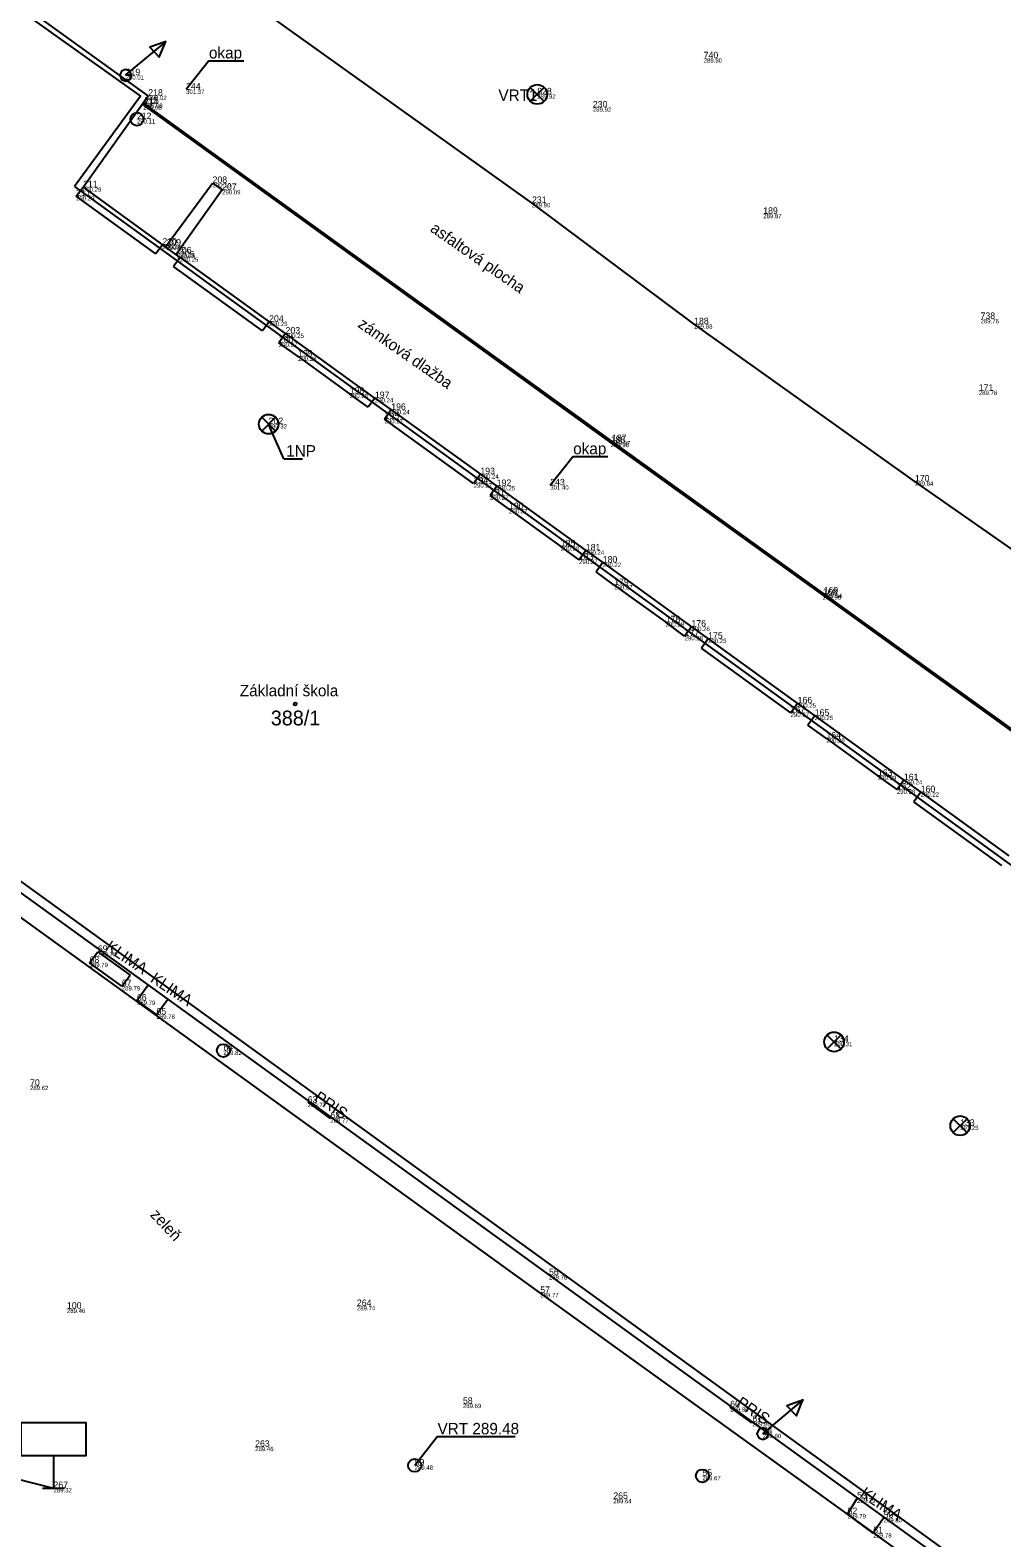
# Model space of a CAD drawing. Extents: x -805057 to -804930, y -994399 to -994240.
# Drawn here: x -805017.71 to -804995.35, y -994342.6 to -994307.89 of the extents above; entities that cross this region are included whole.
import ezdxf

# ---------------------------------------------------------------- set-up
doc = ezdxf.new("R2010")
doc.units = 0
for name, color, linetype in [('bod cislo', 7, 'Continuous'), ('bod pozice', 7, 'Continuous'), ('bod výška', 7, 'Continuous'), ('budova', 7, 'Continuous'), ('kanalizace', 7, 'Continuous'), ('Katastralni mapa', 7, 'Continuous'), ('klima', 7, 'Continuous'), ('komunikace', 7, 'Continuous'), ('označník', 7, 'Continuous'), ('podlaha', 7, 'Continuous'), ('popis', 7, 'Continuous'), ('PRIS', 7, 'Continuous'), ('svod', 7, 'Continuous'), ('vrt', 7, 'Continuous'), ('zemnění', 7, 'Continuous')]:
    doc.layers.add(name, color=color, linetype=linetype)

msp = doc.modelspace()

# ---------------------------------------------------------------- linework, layer by layer
at = {"layer": 'bod pozice'}
for p, q in [((-805002.21, -994308.54), (-805002.21, -994308.54)), ((-805015.51, -994308.93), (-805015.51, -994308.93)), ((-805014.989, -994309.4), (-805014.989, -994309.4)), ((-805014.989, -994309.4), (-805014.989, -994309.4)), ((-805014.12, -994309.26), (-805014.12, -994309.26)), ((-805006.04, -994309.37), (-805006.04, -994309.37)), ((-805015.1, -994309.62), (-805015.1, -994309.62)), ((-805015.08, -994309.58), (-805015.08, -994309.58)), ((-805004.76, -994309.67), (-805004.76, -994309.67)), ((-805015.25, -994309.94), (-805015.25, -994309.94)), ((-805013.51, -994311.41), (-805013.51, -994311.41)), ((-805016.649, -994311.71), (-805016.649, -994311.71)), ((-805016.49, -994311.509), (-805016.49, -994311.509)), ((-805013.29, -994311.57), (-805013.29, -994311.57)), ((-805006.16, -994311.87), (-805006.16, -994311.87)), ((-805000.84, -994312.12), (-805000.84, -994312.12)), ((-805014.663, -994312.829), (-805014.663, -994312.829)), ((-805014.57, -994312.85), (-805014.57, -994312.85)), ((-805014.33, -994313.03), (-805014.33, -994313.03)), ((-805014.259, -994313.121), (-805014.259, -994313.121)), ((-805012.209, -994314.602), (-805012.209, -994314.602)), ((-804995.84, -994314.54), (-804995.84, -994314.54)), ((-805011.831, -994314.875), (-805011.831, -994314.875)), ((-805002.43, -994314.66), (-805002.43, -994314.66)), ((-805011.983, -994315.085), (-805011.983, -994315.085)), ((-805011.541, -994315.405), (-805011.541, -994315.405)), ((-805010.356, -994316.262), (-805010.356, -994316.262)), ((-804995.88, -994316.19), (-804995.88, -994316.19)), ((-805009.775, -994316.361), (-805009.775, -994316.361)), ((-805009.399, -994316.632), (-805009.399, -994316.632)), ((-805012.22, -994316.96), (-805012.22, -994316.96)), ((-805009.552, -994316.844), (-805009.552, -994316.844)), ((-805004.35, -994317.39), (-805004.35, -994317.39)), ((-805004.32, -994317.35), (-805004.32, -994317.35)), ((-805007.503, -994318.325), (-805007.503, -994318.325)), ((-805007.349, -994318.113), (-805007.349, -994318.113)), ((-805006.972, -994318.385), (-805006.972, -994318.385)), ((-805005.74, -994318.37), (-805005.74, -994318.37)), ((-804997.35, -994318.28), (-804997.35, -994318.28)), ((-805007.125, -994318.597), (-805007.125, -994318.597)), ((-805006.688, -994318.915), (-805006.688, -994318.915)), ((-805005.499, -994319.775), (-805005.499, -994319.775)), ((-805005.077, -994320.08), (-805005.077, -994320.08)), ((-805004.922, -994319.867), (-805004.922, -994319.867)), ((-805004.533, -994320.148), (-805004.533, -994320.148)), ((-805004.269, -994320.666), (-805004.269, -994320.666)), ((-804999.45, -994320.86), (-804999.45, -994320.86)), ((-804999.47, -994320.9), (-804999.47, -994320.9)), ((-805003.085, -994321.522), (-805003.085, -994321.522)), ((-805002.648, -994321.838), (-805002.648, -994321.838)), ((-805002.492, -994321.622), (-805002.492, -994321.622)), ((-805002.108, -994321.9), (-805002.108, -994321.9)), ((-805000.21, -994323.601), (-805000.21, -994323.601)), ((-805000.049, -994323.387), (-805000.049, -994323.387)), ((-804999.655, -994323.672), (-804999.655, -994323.672)), ((-804999.387, -994324.195), (-804999.387, -994324.195)), ((-804998.201, -994325.054), (-804998.201, -994325.054)), ((-804997.764, -994325.371), (-804997.764, -994325.371)), ((-804997.604, -994325.154), (-804997.604, -994325.154)), ((-804997.217, -994325.433), (-804997.217, -994325.433)), ((-805016.15, -994329.11), (-805016.15, -994329.11)), ((-805016.34, -994329.36), (-805016.34, -994329.36)), ((-805015.598, -994329.896), (-805015.598, -994329.896)), ((-805015.25, -994330.23), (-805015.25, -994330.23)), ((-805014.8, -994330.55), (-805014.8, -994330.55)), ((-804999.21, -994331.18), (-804999.21, -994331.18)), ((-805013.26, -994331.38), (-805013.26, -994331.38)), ((-805011.32, -994332.58), (-805011.32, -994332.58)), ((-805010.8, -994332.94), (-805010.8, -994332.94)), ((-804996.31, -994333.11), (-804996.31, -994333.11)), ((-805005.77, -994336.55), (-805005.77, -994336.55)), ((-805005.97, -994336.96), (-805005.97, -994336.96)), ((-805016.86, -994337.32), (-805016.86, -994337.32)), ((-805010.19, -994337.26), (-805010.19, -994337.26)), ((-805007.75, -994339.51), (-805007.75, -994339.51)), ((-805001.6, -994339.59), (-805001.6, -994339.59)), ((-805001.09, -994339.93), (-805001.09, -994339.93)), ((-805000.85, -994340.2), (-805000.85, -994340.2)), ((-805012.53, -994340.5), (-805012.53, -994340.5)), ((-805008.86, -994340.93), (-805008.86, -994340.93)), ((-805002.24, -994341.17), (-805002.24, -994341.17)), ((-805017.17, -994341.45), (-805017.17, -994341.45)), ((-805004.29, -994341.7), (-805004.29, -994341.7)), ((-804998.68, -994341.69), (-804998.68, -994341.69)), ((-804998.9, -994342.05), (-804998.9, -994342.05)), ((-804998.07, -994342.14), (-804998.07, -994342.14)), ((-804998.31, -994342.49), (-804998.31, -994342.49))]:
    msp.add_line(p, q, dxfattribs=at)
at = {"layer": 'budova'}
for p, q in [((-805014.989, -994309.4), (-805021.089, -994305.009)), ((-805016.49, -994311.509), (-805014.989, -994309.4)), ((-805016.649, -994311.71), (-805016.49, -994311.509)), ((-805014.814, -994313.037), (-805016.649, -994311.71)), ((-805016.49, -994311.509), (-805014.663, -994312.829)), ((-805014.663, -994312.829), (-805014.814, -994313.037)), ((-805014.259, -994313.121), (-805014.663, -994312.829)), ((-805014.259, -994313.121), (-805014.41, -994313.33)), ((-805014.259, -994313.121), (-805012.209, -994314.602)), ((-805012.36, -994314.812), (-805014.41, -994313.33)), ((-805012.209, -994314.602), (-805012.36, -994314.812)), ((-805011.831, -994314.875), (-805012.209, -994314.602)), ((-805012.031, -994314.731), (-805012.013, -994314.744)), ((-805011.831, -994314.875), (-805011.983, -994315.085)), ((-805009.775, -994316.361), (-805011.831, -994314.875)), ((-805011.541, -994315.405), (-805011.983, -994315.085)), ((-805011.541, -994315.405), (-805010.356, -994316.262)), ((-805009.928, -994316.572), (-805010.356, -994316.262)), ((-805009.775, -994316.361), (-805009.928, -994316.572)), ((-805009.775, -994316.361), (-805009.399, -994316.632)), ((-805009.399, -994316.632), (-805009.552, -994316.844)), ((-805009.399, -994316.632), (-805009.399, -994316.632)), ((-805009.399, -994316.632), (-805007.349, -994318.113)), ((-805007.503, -994318.326), (-805009.552, -994316.844)), ((-805007.349, -994318.113), (-805007.503, -994318.326)), ((-805007.349, -994318.113), (-805006.972, -994318.385)), ((-805006.972, -994318.385), (-805007.126, -994318.599)), ((-805006.972, -994318.385), (-805004.922, -994319.867)), ((-804995.51, -994343.96), (-805030.423, -994318.706)), ((-805006.688, -994318.915), (-805007.126, -994318.599)), ((-805006.688, -994318.915), (-805005.499, -994319.776)), ((-805005.077, -994320.081), (-805005.499, -994319.776)), ((-805004.922, -994319.867), (-805005.077, -994320.081)), ((-805004.922, -994319.867), (-805004.533, -994320.148)), ((-805004.533, -994320.148), (-805004.688, -994320.362)), ((-805004.533, -994320.148), (-805002.492, -994321.622)), ((-805004.269, -994320.666), (-805004.688, -994320.362)), ((-805004.269, -994320.666), (-805003.085, -994321.521)), ((-805002.648, -994321.838), (-805003.085, -994321.521)), ((-805002.492, -994321.622), (-805002.648, -994321.838)), ((-805002.492, -994321.622), (-805002.108, -994321.9)), ((-805002.108, -994321.9), (-805002.264, -994322.116)), ((-805002.108, -994321.9), (-805000.049, -994323.387)), ((-805000.206, -994323.604), (-805002.264, -994322.116)), ((-805000.049, -994323.387), (-805000.206, -994323.604)), ((-805000.049, -994323.387), (-804999.655, -994323.672)), ((-804999.655, -994323.672), (-804999.813, -994323.889)), ((-804999.387, -994324.197), (-804999.813, -994323.889)), ((-804999.655, -994323.672), (-804997.604, -994325.154)), ((-804999.387, -994324.197), (-804998.202, -994325.054)), ((-804997.762, -994325.372), (-804998.202, -994325.054)), ((-804997.604, -994325.154), (-804997.762, -994325.372)), ((-804997.604, -994325.154), (-804997.217, -994325.433)), ((-804997.217, -994325.433), (-804997.375, -994325.652)), ((-804995.351, -994327.116), (-804997.375, -994325.652)), ((-804997.217, -994325.433), (-804995.192, -994326.897))]:
    msp.add_line(p, q, dxfattribs=at)
at = {"layer": 'kanalizace'}
msp.add_circle((-805002.24, -994341.17), 0.15, dxfattribs=at)
at = {"layer": 'Katastralni mapa'}
for points in [[(-805020.62, -994305.52), (-805015.17, -994309.41)], [(-805015.17, -994309.41), (-805016.69, -994311.49)], [(-805016.69, -994311.49), (-804992.96, -994328.69)], [(-805030.18, -994318.62), (-804995.54, -994343.69)]]:
    msp.add_lwpolyline(points, dxfattribs=at)
msp.add_circle((-805011.608, -994323.403), 0.0355, dxfattribs=at)
at = {"layer": 'klima'}
for p, q in [((-805016.34, -994329.36), (-805016.15, -994329.11)), ((-805016.15, -994329.11), (-805015.408, -994329.646)), ((-805015.598, -994329.896), (-805016.34, -994329.36)), ((-805015.598, -994329.896), (-805015.408, -994329.646)), ((-805015.25, -994330.23), (-805014.989, -994329.87)), ((-805014.8, -994330.55), (-805015.25, -994330.23)), ((-805014.8, -994330.55), (-805014.542, -994330.194)), ((-804998.9, -994342.05), (-804998.67, -994341.674)), ((-804998.31, -994342.49), (-804998.9, -994342.05)), ((-804998.055, -994342.119), (-804998.31, -994342.49))]:
    msp.add_line(p, q, dxfattribs=at)
at = {"layer": 'komunikace'}
for p, q in [((-805006.16, -994311.87), (-805012.81, -994307.11)), ((-805015.13, -994309.598), (-805004.35, -994317.39)), ((-805004.32, -994317.35), (-805015.104, -994309.562)), ((-805014.592, -994312.88), (-805013.51, -994311.41)), ((-805013.51, -994311.41), (-805013.29, -994311.57)), ((-805013.29, -994311.57), (-805014.349, -994313.056)), ((-805002.43, -994314.66), (-805006.16, -994311.87)), ((-804997.35, -994318.28), (-805002.43, -994314.66)), ((-805004.35, -994317.39), (-804999.47, -994320.9)), ((-804999.45, -994320.86), (-805004.32, -994317.35)), ((-804990.55, -994323.04), (-804997.35, -994318.28)), ((-804991.576, -994326.53), (-804999.45, -994320.86)), ((-804999.47, -994320.9), (-804991.604, -994326.571)), ((-805025.46, -994322.87), (-805005.97, -994336.96)), ((-805005.97, -994336.96), (-804995.46, -994344.53))]:
    msp.add_line(p, q, dxfattribs=at)
at = {"layer": 'označník'}
for p, q in [((-805017.17, -994340.7), (-805017.17, -994341.45)), ((-805018.47, -994341.12), (-805017.17, -994341.45)), ((-805017.42, -994341.45), (-805016.92, -994341.45))]:
    msp.add_line(p, q, dxfattribs=at)
msp.add_lwpolyline([(-805017.92, -994340.7), (-805016.42, -994340.7), (-805016.42, -994339.95), (-805017.92, -994339.95)], close=True, dxfattribs=at)
at = {"layer": 'podlaha'}
for p, q in [((-805006.199, -994309.528), (-805005.882, -994309.212)), ((-805005.882, -994309.531), (-805006.199, -994309.212)), ((-805012.379, -994317.118), (-805012.062, -994316.802)), ((-805012.062, -994317.121), (-805012.379, -994316.802)), ((-804999.369, -994331.338), (-804999.052, -994331.022)), ((-804999.052, -994331.341), (-804999.369, -994331.022)), ((-804996.469, -994333.268), (-804996.152, -994332.952)), ((-804996.152, -994333.271), (-804996.469, -994332.952))]:
    msp.add_line(p, q, dxfattribs=at)
for centre in [(-805006.04, -994309.37), (-805012.22, -994316.96), (-804999.21, -994331.18), (-804996.31, -994333.11)]:
    msp.add_circle(centre, 0.225, dxfattribs=at)
at = {"layer": 'popis'}
for p, q in [((-805013.593, -994308.596), (-805014.12, -994309.26)), ((-805013.593, -994308.596), (-805012.794, -994308.596)), ((-805011.873, -994317.758), (-805012.22, -994316.96)), ((-805005.213, -994317.706), (-805005.74, -994318.37)), ((-805005.213, -994317.706), (-805004.414, -994317.706)), ((-805011.873, -994317.758), (-805011.442, -994317.758)), ((-805008.333, -994340.266), (-805008.86, -994340.93)), ((-805008.333, -994340.266), (-805006.546, -994340.266))]:
    msp.add_line(p, q, dxfattribs=at)
at = {"layer": 'PRIS'}
for p, q in [((-805011.312, -994332.569), (-805011.293, -994332.543)), ((-805010.8, -994332.94), (-805011.312, -994332.569)), ((-805010.8, -994332.94), (-805010.781, -994332.914)), ((-805001.6, -994339.59), (-805001.583, -994339.567)), ((-805001.104, -994339.949), (-805001.6, -994339.59)), ((-805001.104, -994339.949), (-805001.087, -994339.926))]:
    msp.add_line(p, q, dxfattribs=at)
at = {"layer": 'svod'}
for centre in [(-805015.25, -994309.94), (-805013.26, -994331.38)]:
    msp.add_circle(centre, 0.15, dxfattribs=at)
at = {"layer": 'vrt'}
msp.add_circle((-805008.86, -994340.93), 0.15, dxfattribs=at)
at = {"layer": 'zemnění'}
for p, q in [((-805015.51, -994308.93), (-805014.626, -994308.189)), ((-805000.85, -994340.2), (-804999.966, -994339.459))]:
    msp.add_line(p, q, dxfattribs=at)
for points in [[(-805014.574, -994308.15), (-805014.954, -994308.286), (-805014.738, -994308.514), (-805014.586, -994308.151)], [(-804999.914, -994339.42), (-805000.294, -994339.556), (-805000.078, -994339.784), (-804999.926, -994339.421)]]:
    msp.add_lwpolyline(points, close=True, dxfattribs=at)
for points in [[(-805015.376, -994308.93), (-805015.415, -994308.835), (-805015.51, -994308.796), (-805015.605, -994308.835), (-805015.644, -994308.93), (-805015.605, -994309.025), (-805015.51, -994309.064), (-805015.415, -994309.025), (-805015.376, -994308.93), (-805015.51, -994308.93)], [(-805000.716, -994340.2), (-805000.755, -994340.105), (-805000.85, -994340.066), (-805000.945, -994340.105), (-805000.984, -994340.2), (-805000.945, -994340.295), (-805000.85, -994340.334), (-805000.755, -994340.295), (-805000.716, -994340.2), (-805000.85, -994340.2)]]:
    msp.add_lwpolyline(points, dxfattribs=at)

# ---------------------------------------------------------------- texts
at = {"layer": 'bod cislo'}
for s, p in [('740    ', (-805002.21, -994308.54)), ('219    ', (-805015.51, -994308.93)), ('218    ', (-805014.989, -994309.4)), ('244    ', (-805014.12, -994309.26)), ('828    ', (-805006.04, -994309.37)), ('214    ', (-805015.1, -994309.62)), ('215    ', (-805015.08, -994309.58)), ('230    ', (-805004.76, -994309.67)), ('212    ', (-805015.25, -994309.94)), ('211    ', (-805016.49, -994311.509)), ('208    ', (-805013.51, -994311.41)), ('207    ', (-805013.29, -994311.57)), ('211    ', (-805016.649, -994311.71)), ('231    ', (-805006.16, -994311.87)), ('189    ', (-805000.84, -994312.12)), ('210    ', (-805014.663, -994312.829)), ('209    ', (-805014.57, -994312.85)), ('206    ', (-805014.33, -994313.03)), ('205    ', (-805014.259, -994313.121)), ('204    ', (-805012.209, -994314.602)), ('188    ', (-805002.43, -994314.66)), ('738    ', (-804995.84, -994314.54)), ('200    ', (-805011.983, -994315.085)), ('203    ', (-805011.831, -994314.875)), ('199    ', (-805011.541, -994315.405)), ('198    ', (-805010.356, -994316.262)), ('197    ', (-805009.775, -994316.361)), ('171    ', (-804995.88, -994316.19)), ('195    ', (-805009.552, -994316.844)), ('196    ', (-805009.399, -994316.632)), ('202    ', (-805012.22, -994316.96)), ('186    ', (-805004.35, -994317.39)), ('187    ', (-805004.32, -994317.35)), ('193    ', (-805007.349, -994318.113)), ('194    ', (-805007.503, -994318.325)), ('192    ', (-805006.972, -994318.385)), ('243    ', (-805005.74, -994318.37)), ('170    ', (-804997.35, -994318.28)), ('191    ', (-805007.125, -994318.597)), ('190    ', (-805006.688, -994318.915)), ('185    ', (-805005.499, -994319.775)), ('181    ', (-805004.922, -994319.867)), ('183    ', (-805005.077, -994320.08)), ('180    ', (-805004.533, -994320.148)), ('179    ', (-805004.269, -994320.666)), ('168    ', (-804999.47, -994320.9)), ('169    ', (-804999.45, -994320.86)), ('178    ', (-805003.085, -994321.522)), ('176    ', (-805002.492, -994321.622)), ('177    ', (-805002.648, -994321.838)), ('175    ', (-805002.108, -994321.9)), ('166    ', (-805000.049, -994323.387)), ('167    ', (-805000.21, -994323.601)), ('165    ', (-804999.655, -994323.672)), ('164    ', (-804999.387, -994324.195)), ('163    ', (-804998.201, -994325.054)), ('161    ', (-804997.604, -994325.154)), ('162    ', (-804997.764, -994325.371)), ('160    ', (-804997.217, -994325.433)), ('69    ', (-805016.15, -994329.11)), ('68    ', (-805016.34, -994329.36)), ('67    ', (-805015.598, -994329.896)), ('66    ', (-805015.25, -994330.23)), ('65    ', (-805014.8, -994330.55)), ('64    ', (-805013.26, -994331.38)), ('134    ', (-804999.21, -994331.18)), ('70    ', (-805017.71, -994332.19)), ('63    ', (-805011.32, -994332.58)), ('62    ', (-805010.8, -994332.94)), ('133    ', (-804996.31, -994333.11)), ('56    ', (-805005.77, -994336.55)), ('57    ', (-805005.97, -994336.96)), ('100    ', (-805016.86, -994337.32)), ('264    ', (-805010.19, -994337.26)), ('58    ', (-805007.75, -994339.51)), ('60    ', (-805001.6, -994339.59)), ('61    ', (-805001.09, -994339.93)), ('54    ', (-805000.85, -994340.2)), ('263    ', (-805012.53, -994340.5)), ('59    ', (-805008.86, -994340.93)), ('267    ', (-805017.17, -994341.45)), ('55    ', (-805002.24, -994341.17)), ('265    ', (-805004.29, -994341.7)), ('53    ', (-804998.68, -994341.69)), ('52    ', (-804998.9, -994342.05)), ('50    ', (-804998.07, -994342.14)), ('51    ', (-804998.31, -994342.49))]:
    msp.add_text(s, height=0.15, dxfattribs=at).set_placement(p)
at = {"layer": 'bod výška'}
for s, p in [('289.90  ', (-805002.21, -994308.64)), ('290.01  ', (-805015.51, -994309.03)), ('290.02  ', (-805014.989, -994309.5)), ('301.37  ', (-805014.12, -994309.36)), ('289.92  ', (-805006.04, -994309.47)), ('290.08  ', (-805015.1, -994309.72)), ('290.08  ', (-805015.08, -994309.68)), ('289.92  ', (-805004.76, -994309.77)), ('290.11  ', (-805015.25, -994310.04)), ('290.10  ', (-805013.51, -994311.51)), ('290.29  ', (-805016.649, -994311.81)), ('290.29  ', (-805016.49, -994311.609)), ('290.09  ', (-805013.29, -994311.67)), ('289.90  ', (-805006.16, -994311.97)), ('289.87  ', (-805000.84, -994312.22)), ('290.26  ', (-805014.663, -994312.929)), ('290.25  ', (-805014.57, -994312.95)), ('290.25  ', (-805014.33, -994313.13)), ('290.25  ', (-805014.259, -994313.221)), ('290.25  ', (-805012.209, -994314.702)), ('289.76  ', (-804995.84, -994314.64)), ('290.25  ', (-805011.831, -994314.975)), ('289.88  ', (-805002.43, -994314.76)), ('290.27  ', (-805011.983, -994315.185)), ('290.28  ', (-805011.541, -994315.505)), ('290.28  ', (-805010.356, -994316.362)), ('289.78  ', (-804995.88, -994316.29)), ('290.24  ', (-805009.775, -994316.461)), ('290.24  ', (-805009.399, -994316.732)), ('290.32  ', (-805012.22, -994317.06)), ('290.27  ', (-805009.552, -994316.944)), ('289.98  ', (-805004.35, -994317.49)), ('289.97  ', (-805004.32, -994317.45)), ('290.27  ', (-805007.503, -994318.425)), ('290.24  ', (-805007.349, -994318.213)), ('290.25  ', (-805006.972, -994318.485)), ('301.40  ', (-805005.74, -994318.47)), ('289.84  ', (-804997.35, -994318.38)), ('290.27  ', (-805007.125, -994318.697)), ('290.27  ', (-805006.688, -994319.015)), ('290.28  ', (-805005.499, -994319.875)), ('290.27  ', (-805005.077, -994320.18)), ('290.24  ', (-805004.922, -994319.967)), ('290.22  ', (-805004.533, -994320.248)), ('290.27  ', (-805004.269, -994320.766)), ('289.94  ', (-804999.45, -994320.96)), ('289.96  ', (-804999.47, -994321)), ('290.28  ', (-805003.085, -994321.622)), ('290.28  ', (-805002.648, -994321.938)), ('290.26  ', (-805002.492, -994321.722)), ('290.25  ', (-805002.108, -994322)), ('290.27  ', (-805000.21, -994323.701)), ('290.25  ', (-805000.049, -994323.487)), ('290.25  ', (-804999.655, -994323.772)), ('290.29  ', (-804999.387, -994324.295)), ('290.29  ', (-804998.201, -994325.154)), ('290.28  ', (-804997.764, -994325.471)), ('290.24  ', (-804997.604, -994325.254)), ('290.22  ', (-804997.217, -994325.533)), ('289.78  ', (-805016.15, -994329.21)), ('289.79  ', (-805016.34, -994329.46)), ('289.79  ', (-805015.598, -994329.996)), ('289.79  ', (-805015.25, -994330.33)), ('289.78  ', (-805014.8, -994330.65)), ('290.31  ', (-804999.21, -994331.28)), ('289.82  ', (-805013.26, -994331.48)), ('289.62  ', (-805017.71, -994332.29)), ('289.77  ', (-805011.32, -994332.68)), ('289.77  ', (-805010.8, -994333.04)), ('291.25  ', (-804996.31, -994333.21)), ('289.76  ', (-805005.77, -994336.65)), ('289.77  ', (-805005.97, -994337.06)), ('289.46  ', (-805016.86, -994337.42)), ('289.74  ', (-805010.19, -994337.36)), ('289.69  ', (-805007.75, -994339.61)), ('289.80  ', (-805001.6, -994339.69)), ('289.80  ', (-805001.09, -994340.03)), ('289.80  ', (-805000.85, -994340.3)), ('289.46  ', (-805012.53, -994340.6)), ('289.48  ', (-805008.86, -994341.03)), ('289.67  ', (-805002.24, -994341.27)), ('289.32  ', (-805017.17, -994341.55)), ('289.79  ', (-804998.68, -994341.79)), ('289.64  ', (-805004.29, -994341.8)), ('289.79  ', (-804998.9, -994342.15)), ('289.80  ', (-804998.07, -994342.24)), ('289.78  ', (-804998.31, -994342.59))]:
    msp.add_text(s, height=0.1, dxfattribs=at).set_placement(p)
at = {"layer": 'Katastralni mapa'}
msp.add_text('388/1', height=0.34, dxfattribs=at).set_placement((-805012.17, -994323.894))
at = {"layer": 'popis'}
for s, height, p in [('okap', 0.2629, (-805013.593, -994308.543)), ('VRT1', 0.2629, (-805006.933, -994309.52)), ('okap', 0.2629, (-805005.213, -994317.653)), ('1NP', 0.2629, (-805011.815, -994317.706)), ('Základní škola', 0.26289, (-805012.884, -994323.224)), ('VRT 289.48', 0.2629, (-805008.333, -994340.213))]:
    msp.add_text(s, height=height, dxfattribs=at).set_placement(p)
for s, height, rotation, p in [('asfaltová plocha', 0.26289, 325.131, (-805008.522, -994312.509)), ('zámková dlažba', 0.26289, 325.131, (-805010.188, -994314.708)), ('KLIMA', 0.2629, 326.0249, (-805015.995, -994329.048)), ('KLIMA', 0.2629, 326.0249, (-805014.96, -994329.781)), ('PRIS', 0.2629, 326.0249, (-805011.195, -994332.516)), ('zeleň', 0.2629, 313.0307, (-805014.961, -994335.173)), ('PRIS', 0.2629, 326.0249, (-805001.482, -994339.546)), ('KLIMA', 0.2629, 326.0249, (-804998.63, -994341.629))]:
    msp.add_text(s, height=height, rotation=rotation, dxfattribs=at).set_placement(p)

doc.saveas('drawing.dxf')
